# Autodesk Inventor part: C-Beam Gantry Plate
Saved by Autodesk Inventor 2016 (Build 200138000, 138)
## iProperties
Created: 2016-03
Part Number: C-Beam Gantry Plate
Material: Generic
Document SubType Name: Modeling
Designer: bongo_000
Density: 1 g/cm^3
Appearance: Default
Author: bongo_000
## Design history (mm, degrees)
feature "CUT-EXTRUDE1"
body "Solid1"
